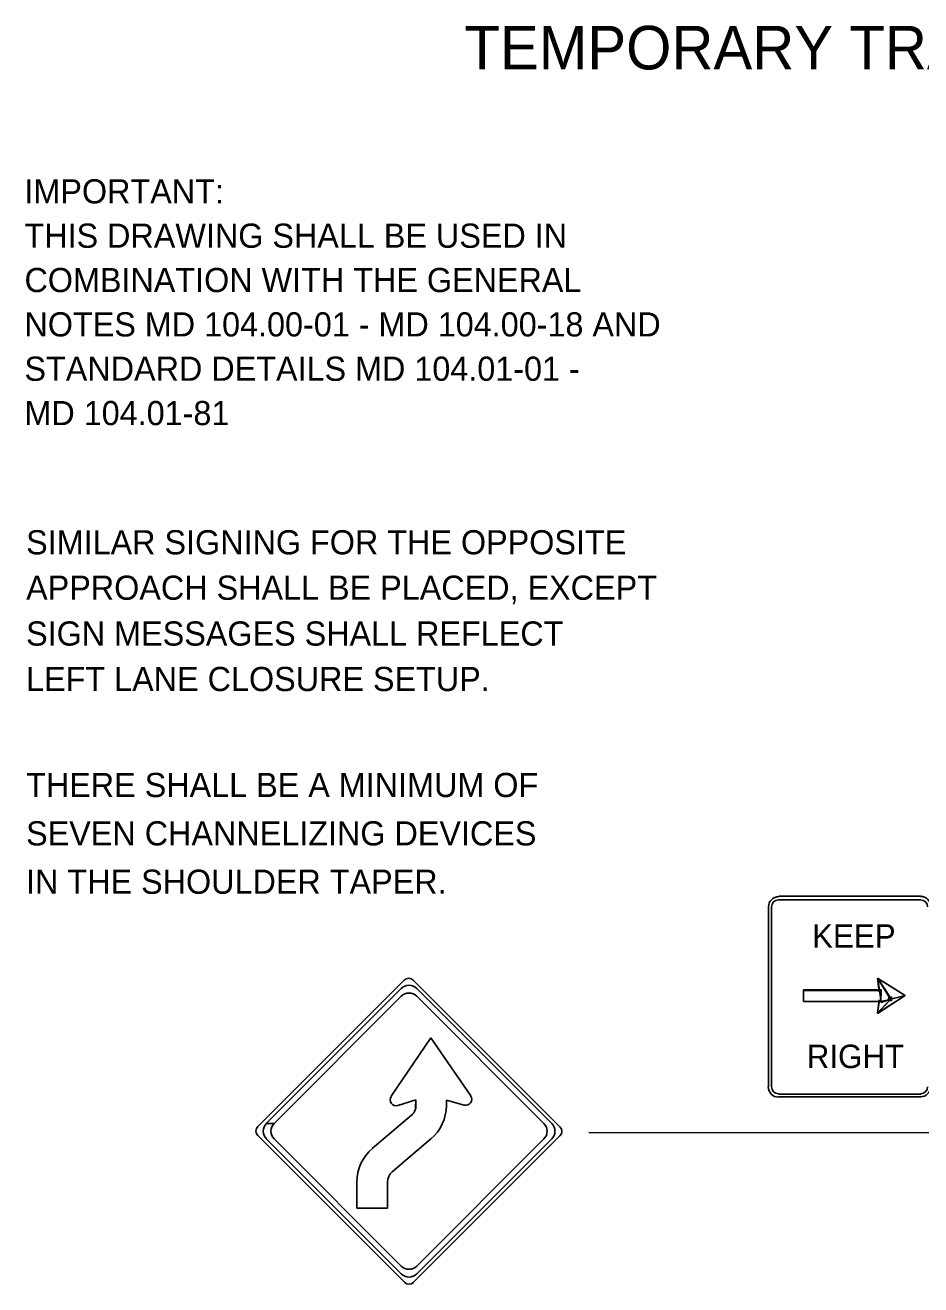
# Model space of a CAD drawing. Extents: x 1531.42 to 1538.58, y 1529.59 to 1539.57.
# Drawn here: x 1531.422 to 1533.644, y 1536.45 to 1539.575 of the extents above; entities that cross this region are included whole.
import ezdxf

# ---------------------------------------------------------------- set-up
doc = ezdxf.new("R2010")
doc.units = 0
for name, color, linetype in [('DETL-DIMS', 7, 'Continuous'), ('DETL-LINE', 7, 'Continuous'), ('DETL-NOTE', 7, 'Continuous'), ('DETL-TITL', 7, 'Continuous')]:
    doc.layers.add(name, color=color, linetype=linetype)

msp = doc.modelspace()

# ---------------------------------------------------------------- linework, layer by layer
at = {"layer": 'DETL-DIMS'}
msp.add_line((1534.3285, 1536.8269), (1532.8205, 1536.8278), dxfattribs=at)
at = {"layer": 'DETL-LINE'}
for p, q in [((1533.6435, 1537.4138), (1533.2912, 1537.4138)), ((1533.6435, 1537.4052), (1533.2912, 1537.4052)), ((1533.2659, 1537.3876), (1533.2659, 1536.941)), ((1533.2736, 1537.3876), (1533.2736, 1536.941)), ((1531.9989, 1536.8428), (1532.362, 1537.2059)), ((1532.02, 1536.8505), (1532.3546, 1537.1853)), ((1532.3844, 1537.2059), (1532.7484, 1536.8421)), ((1532.3934, 1537.1853), (1532.728, 1536.8505)), ((1533.5361, 1537.2105), (1533.5405, 1537.1771)), ((1533.6048, 1537.1674), (1533.5361, 1537.2105)), ((1532.3548, 1537.1658), (1532.0394, 1536.8505)), ((1532.3548, 1537.1658), (1532.3548, 1537.1658)), ((1532.7086, 1536.8507), (1532.3934, 1537.1658)), ((1533.3528, 1537.1533), (1533.3528, 1537.1806)), ((1533.5405, 1537.1806), (1533.3528, 1537.1806)), ((1533.3528, 1537.1771), (1533.3528, 1537.1674)), ((1533.6048, 1537.1674), (1533.5361, 1537.1233)), ((1533.5361, 1537.1233), (1533.5405, 1537.1568)), ((1533.5405, 1537.1533), (1533.3528, 1537.1533)), ((1532.4285, 1537.0629), (1532.3295, 1536.9178)), ((1532.527, 1536.9188), (1532.4285, 1537.0629)), ((1532.3463, 1536.8949), (1532.3909, 1536.9086)), ((1532.3909, 1536.9086), (1532.3899, 1536.8889)), ((1532.4666, 1536.8944), (1532.4666, 1536.9081)), ((1532.4666, 1536.9081), (1532.5107, 1536.8959)), ((1532.5269, 1536.9188), (1532.527, 1536.9188)), ((1533.2912, 1536.9234), (1533.6435, 1536.9234)), ((1533.2912, 1536.9164), (1533.6435, 1536.9164)), ((1532.0394, 1536.8505), (1532.02, 1536.8505)), ((1532.3798, 1536.8706), (1532.2828, 1536.7883)), ((1532.3629, 1536.4564), (1531.9989, 1536.8204)), ((1532.3546, 1536.4773), (1532.02, 1536.8119)), ((1532.0394, 1536.8119), (1532.3548, 1536.4967)), ((1532.332, 1536.7305), (1532.4285, 1536.8122)), ((1532.7484, 1536.8195), (1532.3853, 1536.4564)), ((1532.728, 1536.8119), (1532.3934, 1536.4773)), ((1532.3934, 1536.4967), (1532.7086, 1536.8119)), ((1532.2448, 1536.7056), (1532.2448, 1536.6406)), ((1532.3209, 1536.6406), (1532.3209, 1536.7056)), ((1532.2448, 1536.6406), (1532.3209, 1536.6406))]:
    msp.add_line(p, q, dxfattribs=at)
for points in [[(1533.537, 1537.2097), (1533.5458, 1537.1507), (1533.5704, 1537.1595)], [(1533.537, 1537.2097), (1533.6048, 1537.1674), (1533.5686, 1537.1586)], [(1533.3528, 1537.1533), (1533.3528, 1537.1815), (1533.5458, 1537.1815), (1533.5449, 1537.1533)], [(1533.5361, 1537.1242), (1533.5695, 1537.1586), (1533.6048, 1537.1674)], [(1533.5361, 1537.1242), (1533.5405, 1537.1524), (1533.5678, 1537.1577)], [(1533.5625, 1537.1542), (1533.5713, 1537.1551), (1533.5713, 1537.1639), (1533.5642, 1537.163)]]:
    msp.add_lwpolyline(points, close=True, dxfattribs=at)
for centre, radius, start, end in [((1533.2911, 1537.3875), 0.0252, 90, 180), ((1533.2911, 1537.3875), 0.0176, 90, 180), ((1533.6431, 1537.3875), 0.026, 0, 90), ((1533.6431, 1537.3875), 0.0176, 0, 90), ((1533.2911, 1536.9414), 0.0258, 180, 270), ((1533.2911, 1536.9414), 0.0176, 180, 270), ((1533.6431, 1536.9414), 0.0176, 270, 0), ((1533.6431, 1536.9414), 0.025, 270, 0), ((1532.342, 1536.9093), 0.0149, 145.7397, 286.8976), ((1532.5146, 1536.9104), 0.0149, 254.5104, 34.2603), ((1532.3588, 1536.8951), 0.0325, 310.3349, 10.7451), ((1532.3583, 1536.8946), 0.1083, 310.3349, 0), ((1532.3531, 1536.7055), 0.1083, 130.3349, 180), ((1532.3531, 1536.7055), 0.0325, 130.3348, 180)]:
    msp.add_arc(centre, radius, start, end, dxfattribs=at)
for centre, major_axis, start_param, end_param in [((1532.3741, 1537.1658), (-0.0273, 0), 3.926991, 5.497787), ((1532.3733, 1537.1946), (-0.0159, 0), 3.926991, 5.497787), ((1532.3741, 1537.1465), (-0.0273, 0), 3.926991, 5.497787), ((1532.0102, 1536.8315), (-0.0159, 0), 5.497787, 7.068584), ((1532.0395, 1536.8312), (-0.0273, 0), 5.497787, 7.068584), ((1532.0588, 1536.8312), (-0.0273, 0), 5.497787, 7.068584), ((1532.6894, 1536.8312), (-0.0273, 0), 2.356195, 3.926991), ((1532.7087, 1536.8312), (-0.0273, 0), 2.356195, 3.926991), ((1532.7372, 1536.8307), (-0.0159, 0), 2.356195, 3.926991), ((1532.3741, 1536.5159), (-0.0273, 0), 0.785398, 2.356194), ((1532.3741, 1536.4966), (-0.0273, 0), 0.785398, 2.356194), ((1532.3741, 1536.4677), (-0.0159, 0), 0.785398, 2.356194)]:
    msp.add_ellipse(centre, major_axis=major_axis, ratio=0.999977, start_param=start_param, end_param=end_param, dxfattribs=at)

# ---------------------------------------------------------------- texts
for s, p in [('KEEP', (1533.374, 1537.2863)), ('RIGHT', (1533.3608, 1536.9877))]:
    msp.add_text(s, height=0.05813, dxfattribs=at).set_placement(p)
at = {"layer": 'DETL-NOTE'}
for s, p in [('IMPORTANT:', (1531.4199, 1539.1325)), ('THIS DRAWING SHALL BE USED IN', (1531.4199, 1539.0225)), ('COMBINATION WITH THE GENERAL', (1531.4199, 1538.9125)), ('NOTES MD 104.00-01 - MD 104.00-18 AND', (1531.4199, 1538.8025)), ('STANDARD DETAILS MD 104.01-01 -', (1531.4199, 1538.6925)), ('MD 104.01-81', (1531.4199, 1538.5825)), ('SIMILAR SIGNING FOR THE OPPOSITE', (1531.424, 1538.262)), ('APPROACH SHALL BE PLACED, EXCEPT', (1531.424, 1538.1493)), ('SIGN MESSAGES SHALL REFLECT ', (1531.424, 1538.0357)), ('LEFT LANE CLOSURE SETUP.', (1531.424, 1537.9229)), ('THERE SHALL BE A MINIMUM OF ', (1531.424, 1537.66)), ('SEVEN CHANNELIZING DEVICES ', (1531.424, 1537.54)), ('IN THE SHOULDER TAPER.', (1531.424, 1537.42))]:
    msp.add_text(s, height=0.06, dxfattribs=at).set_placement(p)
at = {"layer": 'DETL-TITL'}
msp.add_text('TEMPORARY TRAFFIC CONTROL TYPICAL APPLICATION', height=0.108, dxfattribs=at).set_placement((1532.5115, 1539.465))

doc.saveas('drawing.dxf')
